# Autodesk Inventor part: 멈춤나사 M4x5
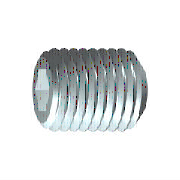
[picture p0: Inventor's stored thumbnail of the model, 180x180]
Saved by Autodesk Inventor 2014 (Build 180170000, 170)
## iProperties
IsCustomPart: 1
Created: 2012-02
Part Number: 멈춤나사 M4x5
Material: 강철, 연강
Description: 6각 소켓 머리 없는 멈춤 나사
Document SubType Name: Modeling
Standard: KS B 1028
Designer: mduedu
Standards Organization: KS
Language: ko-KR
Size Designation: 납작점M4x5
Categories: <MemberInstance><Categories><Category DisplayName="조임쇠" InternalName="e4da775c-781d-43d5-af7c-5136215cf5a6" Mnemonic="FSTN"><Category DisplayName="볼트" InternalN
Density: 1 g/cm^3
Appearance: Steel
Author: mduedu
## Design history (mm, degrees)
sketch "스케치1"
  geometry: L1 (0, 0)-(1.833, 0); L2 (5, 1.155)-(5, 2); L3 (5, 2)-(0, 2); L4 (5, 1.155)-(2.5, 1.155); L5 (2.5, 1.155)-(1.833, 0); L6 (0, -0.4)-(0, 2.4) reference; L7 (0, 2)-(0, 0)
  constraints: 13 end point, 3 parallel, 1 collinear, 1 perpendicular, 1 point on line
  dimensions: "d0" = 2.5 distance of L2.start L4.end (= INTI); "d1" = 60 deg angle of L5 L1; "d2" = 4 diameter of L3 L1 (= NND); "d3" = 2.3094 diameter of L4 L1 (= 1.1547 x SW); "d5" = 5 distance from line of L2 L3.end (= NLG)
revolve "본체" sketch "스케치1" stored, may be unused: angle "d6" = 90 deg
sketch "스케치2"
  geometry: L1 (-0.577, 1)-(0.577, 1); L2 (0.577, 1)-(1.155, 0); L3 (1.155, 0)-(0.577, -1); L4 (0.577, -1)-(-0.577, -1); L5 (-0.577, -1)-(-1.155, 0); L6 (-1.155, 0)-(-0.577, 1); A1 r 1.155 centre (0, 0) between (-0.577, 1) and (0.577, 1) reference; 2 further points
  constraints: 12 end point, 2 point on circle, 1 coincident, 1 horizontal, 11 other
extrude "슬롯" join sketch "스케치2" taper "d9" = 0 deg; stored distance "d21" = 10
workaxis "Work Axis1"
workplane "Work Plane1"
workaxis "Work Axis2"
sketch "Sketch4"
  geometry: L1 (0, 1.571)-(-0.429, 2) reference; L2 (0, 1.571)-(1.571, 0); 1 further point
  constraints: 2 end point, 1 collinear
workpoint "Work Point1"
body "Solid1"
chamfer "모따기1" distance "d7" = 0.42941 (= -0.5 x GD1 + 0.5 x NND); stored, may be unused: angle "d8" = 45 deg (= FAWI), second distance "d29" = 0.42941 (= -0.5 x GD1 + 0.5 x NND)
feature "스레드" dims "d11" = 5 (= NLG), "d12" = 0
chamfer "모따기2" distance "d13" = 0.42941 (= -0.5 x GD1 + 0.5 x NND); stored, may be unused: angle "d14" = 45 deg (= FAWI), second distance "d30" = 0.42941 (= -0.5 x GD1 + 0.5 x NND)
other parameters: "NND" = 4 [user parameter; used in 5 equation terms], "NLG" = 5 [user parameter; used in 2 equation terms], "INTI" = 2.5 [user parameter; used in 1 equation term], "FAWI" = 45 deg [user parameter; used in 2 equation terms], "SW" = 2 [user parameter; used in 2 equation terms], "GD1" = 3.14117 (= THREADDIA - 1.2269 x PTC) [user parameter; used in 4 equation terms], "d4" = 0, "FAWI1" = 45 deg [user parameter], "d15" = 0, "d31" = 0, "GUL" = 0.42941 (= 0.61345 x PTC) [user parameter], "SPD" = 2.5 [user parameter], "TPU" = 14.28571 (computed from PTC) [user parameter], "TOA" = 30 deg [user parameter], "THREADDIA" = 4 [user parameter; used in 1 equation term], "PTC" = 0.7 [user parameter; used in 4 equation terms], "GAL" = 0.42941 (= 0.61345 x PTC) [user parameter], "E0" = 2.31 (= 1.155 x SW) [user parameter]
